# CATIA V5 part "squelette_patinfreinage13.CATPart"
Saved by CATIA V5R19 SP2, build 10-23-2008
Part number: squelette_patinfreinage13
Bounding box of the stored display mesh (mm): x 10 to 30, y 0 to 20, z 0 to 20
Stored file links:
  G:\Documents\IFMA\COURS\2A\S3\CFAO\ProjetCFAO\squelette_patinfreinage13.CATPart
  Chassis6.CATPart
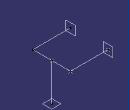
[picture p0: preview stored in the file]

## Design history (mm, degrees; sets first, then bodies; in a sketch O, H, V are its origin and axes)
Parameters
  Largeurchassis_chassis6 = 100 mm
  Longueurchassis_chassis = 320 mm
  Hauteurchassis_chassis6 = 60 mm
  Largeurchassis_chassis6.1 = 100 mm
  Longueurchassis_chassis.1 = 320 mm
  Hauteurchassis_chassis6.1 = 60 mm
Set1
  Point1: (10, 20, 20)
  Point2: (30, 20, 20)
  Line1: type PtPt, FirstPoint Point2, SecondPoint Point1
  Line2: type Angle, RefPoint Point2, Curve Line1, Support xy-plane, Start 0, End 20, Angle 90
  Line3: type PtDir, RefPoint vertex of Line2, Direction Line1, Start 0, End 20
  Point3: type OnCurve, Support Line2, Ratio 0.5
  Line4: type Angle, RefPoint Point3, Curve Line2, Support yz-plane, Start 0, End 20, Angle 90
  Plane1: type Normal, Curve Line1, RefPoint Point1
  Plane2: type Normal, Curve Line3, RefPoint vertex of Line3
  Plane3: type Normal, Curve Line4, RefPoint vertex of Line4
Body1 (main body)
